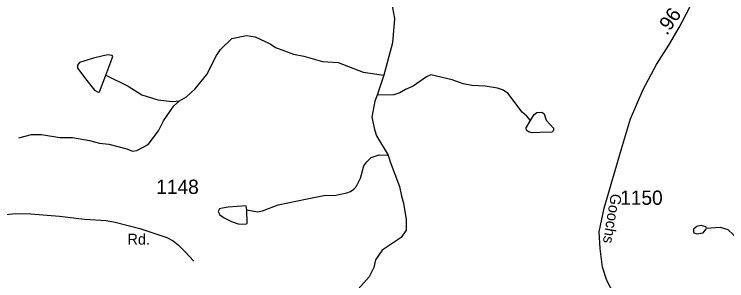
# Model space of a CAD drawing. Extents: x 2056842 to 2160602, y 826753 to 1016856.
# Drawn here: x 2080603 to 2086830, y 928971 to 931304 of the extents above; entities that cross this region are included whole.
import ezdxf

# ---------------------------------------------------------------- set-up
doc = ezdxf.new("R2010")
doc.units = 0
for name, color, linetype in [('Exist Hydrographic Creek Single Shore', 7, 'Continuous'), ('Exist Hydrographic Misc Water Feature', 7, 'Continuous'), ('Exist Hydrographic Pond Under 1500 Sq Ft', 7, 'Continuous'), ('Exist Road Secondary Mileage Hundredths English Label', 7, 'Continuous'), ('Exist Road Secondary Type 41 Attributed', 7, 'Continuous'), ('Exist Road Secondary Type 51 Attributed', 7, 'Continuous'), ('Exist Road Secondary Type 51 Label', 7, 'Continuous'), ('Exist Road Secondary Type 51 Number Label', 7, 'Continuous')]:
    doc.layers.add(name, color=color, linetype=linetype)

msp = doc.modelspace()

# ---------------------------------------------------------------- linework, layer by layer
at = {"layer": 'Exist Hydrographic Creek Single Shore'}
for points in [[(2083910.7, 931402.7), (2083908.8, 931358.8), (2083925.2, 931266.9), (2083907.7, 931054.6), (2083832.6, 930770.4)], [(2083832.6, 930770.4), (2083775.1, 930596.3)], [(2083775.1, 930596.3), (2083755.4, 930544.2), (2083727.8, 930404), (2083750.2, 930296.3), (2083770.3, 930238.4), (2083870.9, 930070.6)], [(2083870.9, 930070.6), (2083887, 930010.6), (2083969.8, 929794.9), (2083986.1, 929710.9), (2084006.2, 929651.1), (2084028.5, 929507.2), (2084026.9, 929415.1), (2083983.3, 929351), (2083817.5, 929238.6), (2083761.6, 929154.5), (2083746.1, 929086.2), (2083704.1, 929006.4), (2083534.8, 928815.6)]]:
    msp.add_lwpolyline(points, dxfattribs=at)
at = {"layer": 'Exist Hydrographic Misc Water Feature'}
for points in [[(2082045.7, 930545.1), (2082107.7, 930581.2), (2082183.3, 930649.5), (2082286.9, 930775.8), (2082370.5, 930942.1), (2082406.4, 930994.2), (2082504, 931090.5), (2082631.8, 931116.9), (2082708.1, 931105.1), (2082840.1, 931043.5), (2082886.3, 931011.6), (2083042.3, 930954.2), (2083134.4, 930936.5), (2083296.6, 930889), (2083432.5, 930881.4), (2083652.7, 930796.1), (2083832.8, 930770.7)], [(2081294.6, 930918.7), (2081172.6, 930882.3), (2081156.8, 930858.2), (2081156.8, 930830.2), (2081237.2, 930724.5)], [(2081403.1, 930771.1), (2081464.6, 930933.2), (2081458.5, 930943.2), (2081418.5, 930947), (2081294.6, 930918.7)], [(2081237.2, 930724.5), (2081305.5, 930638.7), (2081337.5, 930622.8), (2081347.5, 930624.9), (2081403.1, 930771.1)], [(2081403.1, 930771.1), (2081599.3, 930673.6), (2081717.7, 930598), (2081857.7, 930554.5), (2081985.7, 930540.9), (2082045.7, 930545.1)], [(2085116, 930374.7), (2085084, 930412.7), (2085041.8, 930446.5), (2084917.3, 930614), (2084869.1, 930641.9), (2084825.2, 930655.8), (2084717.2, 930675.4), (2084601.1, 930679.1), (2084525, 930694.8), (2084428.9, 930730.6), (2084244.9, 930772), (2084204.9, 930755.8), (2084089.3, 930675.4), (2084021.2, 930645.3), (2083973.2, 930615.1), (2083921.6, 930598.9), (2083775.4, 930596.5)], [(2080642.8, 930222.7), (2080752.7, 930251.1), (2080840.7, 930251.3), (2081000.8, 930225.7), (2081112.8, 930226.2), (2081260.8, 930198.6), (2081349, 930174.9), (2081428.9, 930165.2), (2081587, 930125.6), (2081635, 930105.8), (2081675, 930111.9), (2081773, 930162.3), (2081864.7, 930282.5), (2081906.3, 930370.6), (2081997.8, 930500.9), (2082045.7, 930545.1)], [(2085116, 930374.7), (2085147.8, 930426.8), (2085169.9, 930442.9), (2085213.8, 930447), (2085233.9, 930431), (2085251.9, 930375.1)], [(2085196.4, 930269), (2085128.3, 930266.8), (2085096.3, 930274.7), (2085080.3, 930288.6), (2085078.3, 930310.6), (2085116, 930374.7)], [(2085251.9, 930375.1), (2085316.1, 930305.4), (2085316.3, 930285.3), (2085300.3, 930271.3), (2085196.4, 930269)], [(2082636.7, 929591), (2082728.8, 929575.2), (2082772.7, 929583.4), (2082908.4, 929635.8), (2083162.3, 929686.7), (2083322.2, 929719.2), (2083398.3, 929717.3), (2083510, 929739.7), (2083542, 929751.9), (2083569.9, 929771.9), (2083593.9, 929800), (2083627.7, 929868), (2083659.3, 929976.1), (2083683.3, 930012.2), (2083723.1, 930050.3), (2083791.1, 930074.6), (2083871.1, 930070.8)], [(2082422.6, 929606.3), (2082396.6, 929600.2), (2082384.7, 929576.1), (2082400.9, 929548.3), (2082436.8, 929520.4), (2082503, 929488.6)], [(2082636.7, 929591), (2082628.5, 929626.9), (2082472.7, 929614.4), (2082422.6, 929606.3)], [(2082503, 929488.6), (2082559.2, 929468.8), (2082623.2, 929467), (2082639.2, 929471), (2082636.7, 929591)], [(2086652.9, 929431.6), (2086772.8, 929440), (2086840.9, 929420.2), (2086888.9, 929372.3), (2087037.7, 929166.8), (2087144.2, 929039.2), (2087280.5, 928915.7), (2087368.5, 928851.9), (2087530.9, 928762.4), (2087626.9, 928714.7), (2087829.6, 928543.3), (2088003.7, 928461.9), (2088043.9, 928426), (2088064, 928398), (2088092.1, 928378.2), (2088122.1, 928370.2), (2088232, 928416.7), (2088276, 928398.7), (2088304.1, 928342.9)]]:
    msp.add_lwpolyline(points, dxfattribs=at)
at = {"layer": 'Exist Hydrographic Pond Under 1500 Sq Ft'}
for points in [[(2086568.5, 929445), (2086538.6, 929423), (2086540.9, 929393.1), (2086566.9, 929383.1)], [(2086566.9, 929383.1), (2086624.9, 929391.4), (2086648.7, 929419.4), (2086652.6, 929431.5)], [(2086652.6, 929431.5), (2086646.6, 929443.4), (2086606.5, 929455.4), (2086568.5, 929445)]]:
    msp.add_lwpolyline(points, dxfattribs=at)
at = {"layer": 'Exist Road Secondary Type 41 Attributed'}
msp.add_lwpolyline([(2078920.5, 929604), (2079047, 929615.8), (2079175.8, 929620.9), (2079254.8, 929616.7), (2079503.1, 929579.9), (2079698.4, 929553.9), (2079899.3, 929531.3), (2080196.3, 929540.5), (2080530.2, 929551.1), (2080616.6, 929558.8), (2080749.2, 929558.3), (2080997, 929536.7), (2081216.1, 929511.6), (2081407.1, 929497.5), (2081486.1, 929483.4), (2081700.9, 929428.9), (2081936.1, 929348.7), (2081991.8, 929321.1), (2082036.9, 929285.2), (2082092.4, 929227.7), (2082171.4, 929141.4)], dxfattribs=at)
at = {"layer": 'Exist Road Secondary Type 51 Attributed'}
msp.add_lwpolyline([(2086132.6, 928286.2), (2086054.5, 928454.2), (2085876.7, 928788.4), (2085783.3, 928973.5), (2085744.7, 929089.4), (2085725, 929252.9), (2085714.2, 929400.3), (2085757.3, 929606.9), (2085909, 930127.1), (2085989.8, 930389.4), (2086100.2, 930645.5), (2086215.2, 930862.9), (2086322.9, 931031.8), (2086413.6, 931187.3), (2086505.2, 931359.8), (2086546.5, 931480.2), (2086580.6, 931643.7), (2086604.8, 931824.3), (2086610.2, 932102.8), (2086612.9, 932709.2), (2086615, 933065.8)], dxfattribs=at)

# ---------------------------------------------------------------- texts
at = {"layer": 'Exist Road Secondary Mileage Hundredths English Label'}
msp.add_text('.96', height=125, rotation=55.7509, dxfattribs=at).set_placement((2086307.7, 931112.7))
at = {"layer": 'Exist Road Secondary Type 51 Label'}
for s, rotation, p in [('Goochs', 260.5381, (2085819.1, 929738)), ('Rd.', 359.7874, (2081591.5, 929287.9))]:
    msp.add_text(s, height=95, rotation=rotation, dxfattribs=at).set_placement(p)
at = {"layer": 'Exist Road Secondary Type 51 Number Label'}
for s, p in [('1148', (2081843.7, 929730.9)), ('1150', (2085898.3, 929635.7))]:
    msp.add_text(s, height=125, dxfattribs=at).set_placement(p)

doc.saveas('drawing.dxf')
